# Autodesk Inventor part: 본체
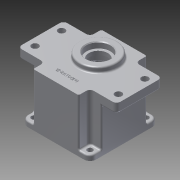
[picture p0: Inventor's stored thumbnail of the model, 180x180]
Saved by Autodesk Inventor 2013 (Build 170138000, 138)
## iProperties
Created: 2015-07
Part Number: 본체
Material: 알루미늄 6061
Document SubType Name: Modeling
Designer: user
Density: 1 g/cm^3
Author: user
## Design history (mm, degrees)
sketch "스케치1"
  geometry: L1 (-45, 45)-(45, 45); L2 (45, 45)-(45, -45); L3 (45, -45)-(-45, -45); L4 (-45, -45)-(-45, 45); 3 further points
  constraints: 8 end point, 2 midpoint, 2 parallel, 1 horizontal, 1 horizontal alignment, 1 perpendicular, 1 vertical alignment
  dimensions: "d0" = 90 distance of L2.end L3.end; "d1" = 90 distance of L1.end L2.end
extrude "돌출1" new body sketch "스케치1" distance "d2" = 70; taper "d3" = 0 deg
sketch "스케치2"
  geometry: L1 (-65, 30)-(65, 30); L2 (65, 30)-(65, -30); L3 (65, -30)-(-65, -30); L4 (-65, -30)-(-65, 30); 3 further points
  constraints: 8 end point, 2 midpoint, 2 parallel, 1 horizontal, 1 horizontal alignment, 1 perpendicular, 1 vertical alignment
  dimensions: "d4" = 130 distance of L2.end L3.end; "d5" = 60 distance of L1.end L2.end
extrude "돌출2" join sketch "스케치2" distance "d6" = 12; taper "d7" = 0 deg
sketch "스케치3"
  geometry: L1 (65, 30)-(65, -30) reference; L2 (45, 30)-(65, 30) reference; L3 (45, 30)-(45, 45) reference; L4 (45, 45)-(-45, 45) reference; L5 (-65, 30)-(-45, 30) reference; L6 (-65, -30)-(-65, 30) reference; L7 (30, 45)-(45, 45); L8 (45, 30)-(30, 30); L9 (30, 45)-(30, 30); L10 (45, 45)-(45, 30); L11 (-45, 45)-(-45, 30); L12 (-30, 45)-(-30, 30); L13 (-45, 30)-(-45, 45); L14 (-30, 45)-(-45, 45); L15 (-45, 30)-(-30, 30); L16 (-30, -45)-(-30, -30); L17 (-45, -30)-(-30, -30); L18 (-30, -45)-(-45, -45); L19 (-45, -45)-(-45, -30); L20 (-45, -45)-(-45, -30); L21 (-45, -30)-(-45, -45); L22 (45, -45)-(45, -30); L23 (45, -30)-(45, -45); L24 (30, -45)-(30, -30); L25 (45, -30)-(30, -30); L26 (30, -45)-(45, -45); L27 (-45, 45)-(-30, 45); L28 (30, 45)-(45, 45); 2 further points
  constraints: 44 end point, 4 parallel, 1 collinear, 1 perpendicular, 1 point on line
  dimensions: "d11" = 90 deg angle of L1 L28; "d12" = 90 deg angle of L1 L8; "d13" = 90 deg angle of L1 L25; "d14" = 90 deg angle of L1 L26; "d15" = 90 deg angle of L1 L15; "d16" = 90 deg angle of L1 L18; "d17" = 90 deg angle of L4 L9; "d18" = 90 deg angle of L4 L12; "d19" = 90 deg angle of L4 L13; "d20" = 90 deg angle of L4 L21; "d21" = 90 deg angle of L2 L22; "d22" = 90 deg angle of L2 L19; "d23" = 35 distance between parallel lines of L1 L24; "d24" = 95 distance between parallel lines of L1 L16; "d25" = 0 distance between parallel lines of L4 L27; "d26" = 75 distance from line of L1.start L26; "d27" = 35 distance from line of L1.start L9; "d28" = 95 distance from line of L1.start L12; "d29" = 75 distance from line of L1.start L18; "d30" = 20 distance from line of L28.end L1; "d31" = 20 distance from line of point (45, -45) L1; "d32" = 90 distance from line of point (45, -45) L4; "d33" = 90 distance from line of L19.start L4
extrude "돌출3" cut sketch "스케치3" distance "d34" = 63; taper "d35" = 0 deg
sketch "스케치4"
  geometry: L1 (65, 30)-(30, 30) reference; L2 (0, 0)-(0, 11); C1 r 25 at (0, 11)
  constraints: 2 end point, 1 centre point, 1 coincident, 1 perpendicular
  dimensions: "d36" = 11 distance of L2.start L2.end; "d37" = 25 radius of C1
extrude "돌출4" join sketch "스케치4" distance "d38" = 7; taper "d39" = 0 deg
sketch "스케치5"
  geometry: 1 further point
hole "구멍1" sketch "스케치5" at (0, 0) diameter "d40" = 78; stored, may be unused: countersink angle "d44" = 90 deg, drill point angle "d46" = 0 deg; dims "d41" = 6, "d42" = 80, "d43" = 9, "d45" = 61
sketch "스케치6"
  geometry: C1 r 25 at (0, 0) reference; 1 further point
hole "구멍2" sketch "스케치6" at (0, 0) diameter "d47" = 25; stored, may be unused: countersink angle "d51" = 90 deg, drill point angle "d53" = 0 deg; dims "d48" = 6, "d49" = 32, "d50" = 8, "d52" = 13
sketch "스케치9"
  geometry: C1 r 40 at (0, 0) reference; C2 r 39 at (0, 0) reference; A1 r 4 centre (-24.749, 24.749) between (-27.462, 21.809) and (-21.809, 27.462); A2 r 3.5 centre (-19.238, 29.836) between (-21.134, 32.777) and (-21.762, 27.412); A3 r 3.5 centre (-29.836, 19.238) between (-27.412, 21.762) and (-32.777, 21.134); A4 r 3.5 centre (-29.836, -19.238) between (-32.777, -21.134) and (-27.412, -21.762); A5 r 4 centre (-24.749, -24.749) between (-21.809, -27.462) and (-27.462, -21.809); A6 r 3.5 centre (-19.238, -29.836) between (-21.762, -27.412) and (-21.134, -32.777); A7 r 3.5 centre (19.238, -29.836) between (21.134, -32.777) and (21.762, -27.412); A8 r 4 centre (24.749, -24.749) between (27.462, -21.809) and (21.809, -27.462); A9 r 3.5 centre (29.836, -19.238) between (27.412, -21.762) and (32.777, -21.134); A10 r 3.5 centre (29.836, 19.238) between (32.777, 21.134) and (27.412, 21.762); A11 r 4 centre (24.749, 24.749) between (21.809, 27.462) and (27.462, 21.809); A12 r 3.5 centre (19.238, 29.836) between (21.762, 27.412) and (21.134, 32.777); A13 r 39 centre (0, 0) between (32.777, 21.134) and (21.134, 32.777); A14 r 39 centre (0, 0) between (-21.134, 32.777) and (-32.777, 21.134); A15 r 39 centre (0, 0) between (-32.777, -21.134) and (-21.134, -32.777); A16 r 39 centre (0, 0) between (21.134, -32.777) and (32.777, -21.134)
  constraints: 40 point on circle, 16 centre point, 5 tangent, 1 coincident, 49 other
  dimensions: "d71" = 4 radius of A1; "d72" = 3.5 radius of A2; "d73" = 3.5 radius of A3; "d76" = 360 deg dimension on C1.centre A2.centre (derived); "d78" = 39 radius of A16; "d79" = 35 distance of A10.end C2.centre; "d80" = 35 distance of A9.start C2.centre
extrude "돌출5" join sketch "스케치9" distance "d81" = 45; taper "d82" = 0 deg
sketch "스케치10"
  geometry: C1 r 39 at (0, 0) reference; A1 r 20.5 centre (0, 11) between (7.402, -8.117) and (-7.402, -8.117); A2 r 14 centre (0, -20) between (-7.402, -8.117) and (7.402, -8.117)
  constraints: 4 point on circle, 2 centre point
  dimensions: "d84" = 20.5 radius of A1; "d86" = 14 radius of A2; "d87" = 10.98533 distance of C1.centre A1.start; "d88" = 11 distance of C1.centre A1.centre; "d89" = 20 distance of C1.centre A2.centre
extrude "돌출6" join sketch "스케치10" distance "d90" = 7; taper "d91" = 0 deg
sketch "스케치11"
  geometry: A1 r 20.5 centre (0, 11) between (7.402, -8.117) and (-7.402, -8.117) reference; 1 further point
hole "구멍5" sketch "스케치11" at (0, 11) diameter "d92" = 35; stored, may be unused: countersink angle "d96" = 90 deg, drill point angle "d98" = 0 deg; dims "d93" = 6, "d94" = 22, "d95" = 7, "d97" = 10
sketch "스케치12"
  geometry: A1 r 14 centre (0, -20) between (-7.402, -8.117) and (7.402, -8.117) reference; 1 further point
hole "구멍6" sketch "스케치12" at (0, -20) diameter "d99" = 19; stored, may be unused: countersink angle "d103" = 90 deg, drill point angle "d105" = 0 deg; dims "d100" = 6, "d101" = 22, "d102" = 7, "d104" = 8
chamfer "모따기1" distance "d106" = 1; stored, may be unused: second distance "d107" = 2, angle "d108" = 45 deg
fillet "모깎기1" dims "d109" = 0.3
fillet "모깎기2" dims "d110" = 0.3
fillet "모깎기3" dims "d111" = 2
fillet "모깎기4" dims "d112" = 8
fillet "모깎기5" dims "d113" = 5
sketch "스케치13"
  geometry: L1 (-60, 30)-(30, 30) reference; L2 (0, 0)-(-55, 0); L3 (-55, 0)-(-55, -17.5); L4 (0, 0)-(0, -20.451); C1 r 4.5 at (-55, -17.5); C2 r 4.5 at (-55, 17.5); C3 r 4.5 at (55, -17.5); C4 r 4.5 at (55, 17.5); 1 further point
  constraints: 6 end point, 4 centre point, 3 symmetric about line, 2 parallel, 1 coincident, 1 perpendicular, 3 other
  dimensions: "d115" = 55 distance of L2.start L2.end; "d116" = 17.5 distance of L2.end L3.end; "d117" = 4.5 radius of C1
extrude "돌출7" cut sketch "스케치13" distance "d118" = 12; taper "d119" = 0 deg
sketch "스케치14"
  geometry: L1 (30, -30)-(30, -45) reference; L2 (37, -45)-(30, -45) reference; L3 (45, -30)-(45, -37) reference; L4 (45, -30)-(30, -30) reference; L5 (30, -45)-(-30, -45) reference; L6 (-30, -45)-(-30, -30) reference; L7 (-30, -30)-(-45, -30) reference; L8 (-45, -37)-(-45, -30) reference; L9 (-30, -45)-(-37, -45) reference; L10 (45, 30)-(45, -30) reference; L11 (30, 30)-(45, 30) reference; L12 (30, 45)-(30, 30) reference; L13 (30, 45)-(37, 45) reference; L14 (45, 37)-(45, 30) reference; L15 (-45, -30)-(-45, 30) reference; L16 (-45, 30)-(-30, 30) reference; L17 (-30, 30)-(-30, 45) reference; L18 (-37, 45)-(-30, 45) reference; L19 (-45, 30)-(-45, 37) reference; L20 (-30, 45)-(30, 45) reference; C1 r 40 at (0, 0) reference; A1 r 8 centre (37, 37) between (45, 37) and (37, 45) reference; A2 r 8 centre (37, -37) between (37, -45) and (45, -37) reference; A3 r 8 centre (-37, -37) between (-45, -37) and (-37, -45) reference; A4 r 8 centre (37, 37) between (45, 37) and (37, 45) reference; A5 r 8 centre (-37, 37) between (-37, 45) and (-45, 37) reference; 1 further point
hole "구멍7" sketch "스케치14" at (37, 37), (37, -37), (-37, -37), (-37, 37) diameter "d120" = 7; stored, may be unused: countersink angle "d124" = 90 deg, drill point angle "d126" = 0 deg; dims "d121" = 6, "d122" = 22, "d123" = 7, "d125" = 8
sketch "스케치15"
  geometry: A1 r 4 centre (-24.749, 24.749) between (-27.462, 21.809) and (-21.809, 27.462) reference; A2 r 4 centre (24.749, 24.749) between (21.809, 27.462) and (27.462, 21.809) reference; A3 r 4 centre (24.749, -24.749) between (27.462, -21.809) and (21.809, -27.462) reference; A4 r 4 centre (-24.749, -24.749) between (-21.809, -27.462) and (-27.462, -21.809) reference
hole "구멍8" sketch "스케치15" at (24.749, 24.749), (24.749, -24.749), (-24.749, -24.749), (-24.749, 24.749) diameter "d127" = 3.459; stored, may be unused: countersink angle "d131" = 90 deg, drill point angle "d133" = 118 deg; dims "d128" = 12, "d129" = 22, "d130" = 7, "d132" = 15
fillet "모깎기7" dims "d134" = 2
fillet "모깎기8" dims "d135" = 3
sketch "스케치17"
  geometry: L1 (-30, -45)-(30, -45) reference; L2 (-60, 30)-(-30, 30) reference; L3 (0, -45)-(0, -30); 2 further points
  constraints: 2 end point, 1 coincident, 1 midpoint, 1 perpendicular, 1 other
  dimensions: "d139" = 15 distance of L3.start L3.end
feature "엠보싱2" sketch "스케치17" dims "d140" = 0.5, "d141" = 0
fillet "모깎기10" dims "d143" = 2
fillet "모깎기11" dims "d144" = 2
fillet "모깎기12" dims "d145" = 2
fillet "모깎기13" dims "d146" = 2
fillet "모깎기14" dims "d147" = 2
fillet "모깎기15" dims "d148" = 2
fillet "모깎기16" dims "d149" = 5
fillet "모깎기17" dims "d150" = 2
node "솔리드1"
node "절단 모서리 투영1"
